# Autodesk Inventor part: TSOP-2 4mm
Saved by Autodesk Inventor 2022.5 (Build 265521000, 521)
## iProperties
Created: 2024-12
Part Number: TSOP-2 4mm
Material: Generic
Document SubType Name: Modeling
Designer: AdminForWorker
Density: 1 g/cm^3
Appearance: Default
Title: TSOP-2 4mm v1
Author: AdminForWorker
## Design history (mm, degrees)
feature "Body1"
feature "lead2" [Body]
feature "opt_lead" [Body]
body "Solid1"
body "Solid2"
body "Solid3"
